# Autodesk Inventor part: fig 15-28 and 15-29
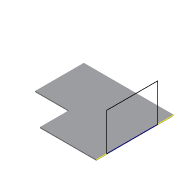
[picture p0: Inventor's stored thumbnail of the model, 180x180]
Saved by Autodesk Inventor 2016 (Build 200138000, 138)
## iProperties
Created: 2005-03
Part Number: fig 15-28 and 15-29
Document SubType Name: Sheet Metal
Designer: CADCIM
Manufacturer: Standard
Standards Organization: Custom
Density: 1 g/cm^3
Sheet Metal Rule: Default
Material: Generic
Appearance: Default
Author: CADCIM
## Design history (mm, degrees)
node "Face1"
  sketch "Sketch1"
    geometry: L1 (29.25, 32.25)-(-19.875, 32.25); L2 (-19.875, 32.25)-(-19.875, 5.625); L3 (-19.875, 5.625)-(-1.5, 5.625); L4 (-1.5, 5.625)-(-1.5, -10.125); L5 (-1.5, -10.125)-(29.25, -10.125); L6 (29.25, -10.125)-(29.25, 32.25)
    constraints: 12 end point, 4 parallel, 1 horizontal, 1 perpendicular
sketch "Sketch2"
  geometry: L1 (-0.5, 42.375)-(-0.5, 0) reference; L2 (-0.5, 5.593)-(-21.049, 5.593); L3 (-21.049, 5.593)-(-21.049, 33.56); L4 (-21.049, 33.56)-(-0.5, 33.56); L5 (-0.5, 33.56)-(-0.5, 5.593)
  constraints: 8 end point, 2 parallel, 1 horizontal, 1 perpendicular, 1 point on line
body "Solid1"
face "Plate1" dims "Thickness" = 0.5
other parameters: "BendRadius" = 0.5 (= Thickness), "BendReliefWidth" = 0.5 (= Thickness), "BendReliefDepth" = 0.25 (= 0.5 x Thickness), "CornerReliefSize" = 2 (= 4 x Thickness), "SeamGap" = 0.01, "MinimumRemnant" = 1 (= 2 x Thickness), "TransitionRadius" = 0.5 (= BendRadius), "d0" = 0.5 (= BendRadius), "JacobiRadiusSize" = 0.5 (= Thickness), "GapSize" = 0.5 (= Thickness)
